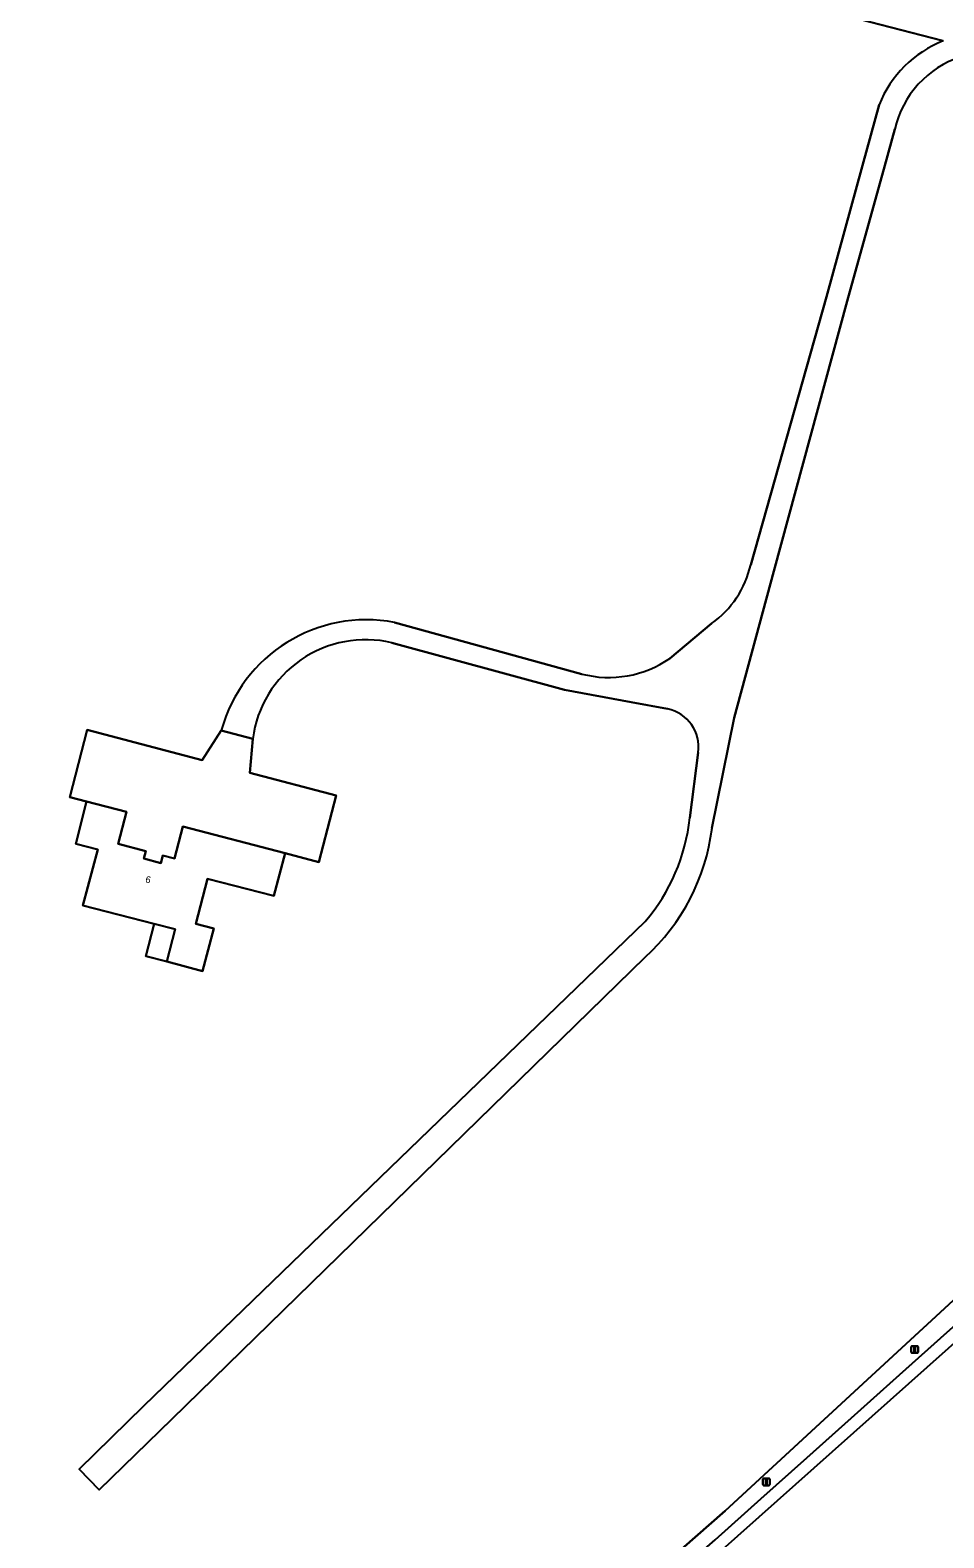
# Model space of a CAD drawing. Extents: x 156502 to 159075, y 384229 to 386100.
# Drawn here: x 158632.4 to 158764.8, y 384551 to 384769.6 of the extents above; entities that cross this region are included whole.
import ezdxf

# ---------------------------------------------------------------- set-up
doc = ezdxf.new("R2010")
doc.units = 0
for name, color, linetype in [('IMGEO_Gemengd_bos', 7, 'Continuous'), ('IMGEO_Groenvoorziening', 7, 'Continuous'), ('IMGEO_Hek', 7, 'Continuous'), ('IMGEO_Lichtmast', 7, 'Continuous'), ('IMGEO_Pand', 7, 'Continuous'), ('IMGEO_Pand_nummerreeks', 7, 'Continuous'), ('IMGEO_Rijbaan_lokaal_gesloten', 7, 'Continuous')]:
    doc.layers.add(name, color=color, linetype=linetype)

msp = doc.modelspace()

# ---------------------------------------------------------------- linework, layer by layer
at = {"layer": 'IMGEO_Gemengd_bos'}
for points in [[(158764.73, 384768.05), (158710.23, 384782.19)], [(158736.83, 384692.1), (158747.83, 384730.95), (158753.03, 384750), (158755.43, 384758.77)], [(158757.72, 384755.24), (158756.27, 384750), (158750.83, 384730.33), (158740.19, 384691.19), (158734.44, 384669.92), (158731.22, 384653.9)], [(158685.23, 384683.75), (158712.37, 384676.27)], [(158725.1, 384678.53), (158731.15, 384683.61)], [(158724.79, 384671.23), (158719.5, 384672.2), (158709.87, 384673.98), (158684.83, 384680.8)], [(158642.2, 384650.81), (158639.02, 384651.67), (158640.59, 384657.79), (158638.16, 384658.42), (158640.7, 384668.17), (158657.35, 384663.78), (158660.11, 384668.09)], [(158664.67, 384666.88), (158664.26, 384661.96), (158676.78, 384658.66), (158674.24, 384649), (158669.35, 384650.29), (158667.72, 384644.13), (158658.12, 384646.57), (158656.41, 384640.05), (158659.02, 384639.38), (158657.39, 384633.2), (158652.23, 384634.57), (158649.19, 384635.37), (158650.39, 384640.06), (158640.05, 384642.69), (158642.2, 384650.81)], [(158728.01, 384655.4), (158729.24, 384664.9)], [(158721.53, 384635.23), (158652.93, 384568.23), (158642.44, 384557.98), (158639.5, 384560.99), (158648.85, 384570.12), (158651.86, 384573.07), (158721.54, 384640.38)], [(158670.56, 384500), (158733.14, 384554.95), (158790.51, 384607.91)]]:
    msp.add_lwpolyline(points, dxfattribs=at)
for centre, radius, start, end in [((158770.77, 384752.69), 16.5, 111.4528, 158.3745), ((158771.71, 384752.09), 14.35, 107.8735, 167.3223), ((158723.03, 384695.18), 14.14, 305.0815, 347.4388), ((158681.15, 384662.32), 21.82, 79.2236, 164.6637), ((158681.01, 384664.77), 16.47, 76.5943, 172.6594), ((158716.27, 384691.29), 15.52, 255.4402, 304.6707), ((158723.59, 384665.65), 5.7, 352.3951, 77.7844), ((158700.4, 384658.39), 27.77, 319.583, 353.8247), ((158701.12, 384657.67), 30.34, 312.2894, 352.863)]:
    msp.add_arc(centre, radius, start, end, dxfattribs=at)
at = {"layer": 'IMGEO_Groenvoorziening'}
for points in [[(158758.39, 384574.66), (158765.24, 384580.8), (158771.71, 384586.55), (158779.13, 384593.12), (158777.49, 384595.03), (158777.92, 384595.4), (158779.58, 384593.53), (158783.29, 384596.87), (158783.37, 384596.78), (158790.87, 384603.43), (158790.51, 384607.91), (158733.14, 384554.95), (158670.56, 384500), (158573.19, 384414.32), (158574.92, 384411.58), (158576.2, 384412.29), (158589.14, 384392.31), (158589.02, 384389.56), (158587.72, 384389.57), (158587.8, 384389.16), (158584.38, 384386.89), (158585.91, 384384.8), (158507.39, 384332.46)], [(158626.52, 384457.73), (158638.91, 384468.6), (158644.8, 384473.78), (158651.86, 384480.04), (158658.95, 384486.33), (158665.86, 384492.38), (158672.54, 384498.34), (158679.43, 384504.34), (158685.79, 384510), (158692.59, 384516.01), (158699.9, 384522.52), (158706.46, 384528.33), (158712.89, 384534.05), (158718.79, 384539.32), (158725.04, 384544.89), (158731.68, 384550.76), (158738.3, 384556.69), (158744.99, 384562.66), (158751.39, 384568.37), (158758.39, 384574.66)]]:
    msp.add_lwpolyline(points, dxfattribs=at)
at = {"layer": 'IMGEO_Hek'}
msp.add_lwpolyline([(158670.56, 384500), (158733.14, 384554.95), (158790.51, 384607.91)], dxfattribs=at)
at = {"layer": 'IMGEO_Lichtmast'}
for p, q in [((158760.09, 384577.94), (158760.09, 384578.74)), ((158760.09, 384578.74), (158760.09, 384577.94)), ((158760.19, 384578.84), (158760.98, 384578.84)), ((158760.98, 384578.84), (158760.19, 384578.84)), ((158761.08, 384578.74), (158761.08, 384577.94)), ((158761.08, 384577.94), (158761.08, 384578.74)), ((158760.98, 384577.84), (158760.19, 384577.84)), ((158760.19, 384577.84), (158760.98, 384577.84)), ((158738.61, 384558.75), (158738.61, 384559.55)), ((158738.61, 384559.55), (158738.61, 384558.75)), ((158738.71, 384559.65), (158739.5, 384559.65)), ((158739.5, 384559.65), (158738.71, 384559.65)), ((158739.5, 384558.65), (158738.71, 384558.65)), ((158738.71, 384558.65), (158739.5, 384558.65)), ((158739.6, 384559.55), (158739.6, 384558.75)), ((158739.6, 384558.75), (158739.6, 384559.55))]:
    msp.add_line(p, q, dxfattribs=at)
for points in [[(158760.51, 384578.71), (158760.66, 384578.71), (158760.66, 384577.96), (158760.51, 384577.96), (158760.51, 384578.71)], [(158739.03, 384559.53), (158739.18, 384559.53), (158739.18, 384558.78), (158739.03, 384558.78), (158739.03, 384559.53)]]:
    msp.add_lwpolyline(points, dxfattribs=at)
for centre, start, end in [((158760.19, 384578.74), 90, 180), ((158760.19, 384578.74), 90, 180), ((158760.98, 384578.74), 0, 90), ((158760.98, 384578.74), 360, 90), ((158760.19, 384577.94), 180, 270), ((158760.19, 384577.94), 180, 270), ((158760.98, 384577.94), 270, 0), ((158760.98, 384577.94), 270, 0), ((158738.71, 384559.55), 90, 180), ((158738.71, 384559.55), 90, 180), ((158738.71, 384558.75), 180, 270), ((158738.71, 384558.75), 180, 270), ((158739.5, 384559.55), 0, 90), ((158739.5, 384559.55), 360, 90), ((158739.5, 384558.75), 270, 0), ((158739.5, 384558.75), 270, 0)]:
    msp.add_arc(centre, 0.1, start, end, dxfattribs=at)
at = {"layer": 'IMGEO_Pand'}
for points in [[(158652.23, 384634.57), (158657.39, 384633.2), (158659.02, 384639.38), (158656.41, 384640.05), (158658.12, 384646.57), (158667.72, 384644.13), (158669.35, 384650.29), (158654.53, 384654.15), (158653.32, 384649.51), (158651.65, 384649.95), (158651.36, 384648.85), (158648.89, 384649.5), (158649.17, 384650.59), (158645.18, 384651.63), (158646.39, 384656.28), (158640.59, 384657.79), (158639.02, 384651.67), (158642.2, 384650.81), (158640.05, 384642.69), (158650.39, 384640.06), (158653.44, 384639.28)], [(158652.23, 384634.57), (158653.44, 384639.28), (158650.39, 384640.06), (158649.19, 384635.37)]]:
    msp.add_lwpolyline(points, close=True, dxfattribs=at)
at = {"layer": 'IMGEO_Rijbaan_lokaal_gesloten'}
for points in [[(158710.23, 384782.19), (158764.73, 384768.05)], [(158755.43, 384758.77), (158753.03, 384750), (158747.83, 384730.95), (158736.83, 384692.1)], [(158750.83, 384730.33), (158756.27, 384750), (158757.72, 384755.24)], [(158731.22, 384653.9), (158734.44, 384669.92), (158740.19, 384691.19), (158750.83, 384730.33)], [(158712.37, 384676.27), (158685.23, 384683.75)], [(158731.15, 384683.61), (158725.1, 384678.53)], [(158684.83, 384680.8), (158709.87, 384673.98), (158719.5, 384672.2), (158724.79, 384671.23)], [(158660.11, 384668.09), (158664.67, 384666.88)], [(158729.24, 384664.9), (158728.01, 384655.4)], [(158721.54, 384640.38), (158651.86, 384573.07), (158648.85, 384570.12), (158639.5, 384560.99), (158642.44, 384557.98), (158652.93, 384568.23), (158721.53, 384635.23)], [(158663.7, 384487.82), (158784.52, 384595.48), (158783.37, 384596.78), (158783.29, 384596.87), (158779.58, 384593.53), (158779.85, 384593.23), (158779.37, 384592.84), (158779.13, 384593.12), (158771.71, 384586.55), (158765.24, 384580.8), (158758.39, 384574.66), (158751.39, 384568.37), (158744.99, 384562.66), (158738.3, 384556.69), (158731.68, 384550.76)]]:
    msp.add_lwpolyline(points, dxfattribs=at)
msp.add_lwpolyline([(158664.67, 384666.88), (158660.11, 384668.09), (158657.35, 384663.78), (158640.7, 384668.17), (158638.16, 384658.42), (158640.59, 384657.79), (158646.39, 384656.28), (158645.18, 384651.63), (158649.17, 384650.59), (158648.89, 384649.5), (158651.36, 384648.85), (158651.65, 384649.95), (158653.32, 384649.51), (158654.53, 384654.15), (158669.35, 384650.29), (158674.24, 384649), (158676.78, 384658.66), (158664.26, 384661.96)], close=True, dxfattribs=at)
for centre, radius, start, end in [((158770.77, 384752.69), 16.5, 111.4528, 158.3745), ((158771.71, 384752.09), 14.35, 107.8735, 167.3223), ((158723.03, 384695.18), 14.14, 305.0815, 347.4388), ((158681.15, 384662.32), 21.82, 79.2236, 164.6637), ((158681.01, 384664.77), 16.47, 76.5943, 172.6594), ((158716.27, 384691.29), 15.52, 255.4402, 304.6707), ((158723.59, 384665.65), 5.7, 352.3951, 77.7844), ((158700.4, 384658.39), 27.77, 319.583, 353.8247), ((158701.12, 384657.67), 30.34, 312.2894, 352.863)]:
    msp.add_arc(centre, radius, start, end, dxfattribs=at)

# ---------------------------------------------------------------- texts
at = {"layer": 'IMGEO_Pand_nummerreeks'}
msp.add_text('6', height=1, rotation=345.3716, dxfattribs=at).set_placement((158649.03, 384646.07))

doc.saveas('drawing.dxf')
